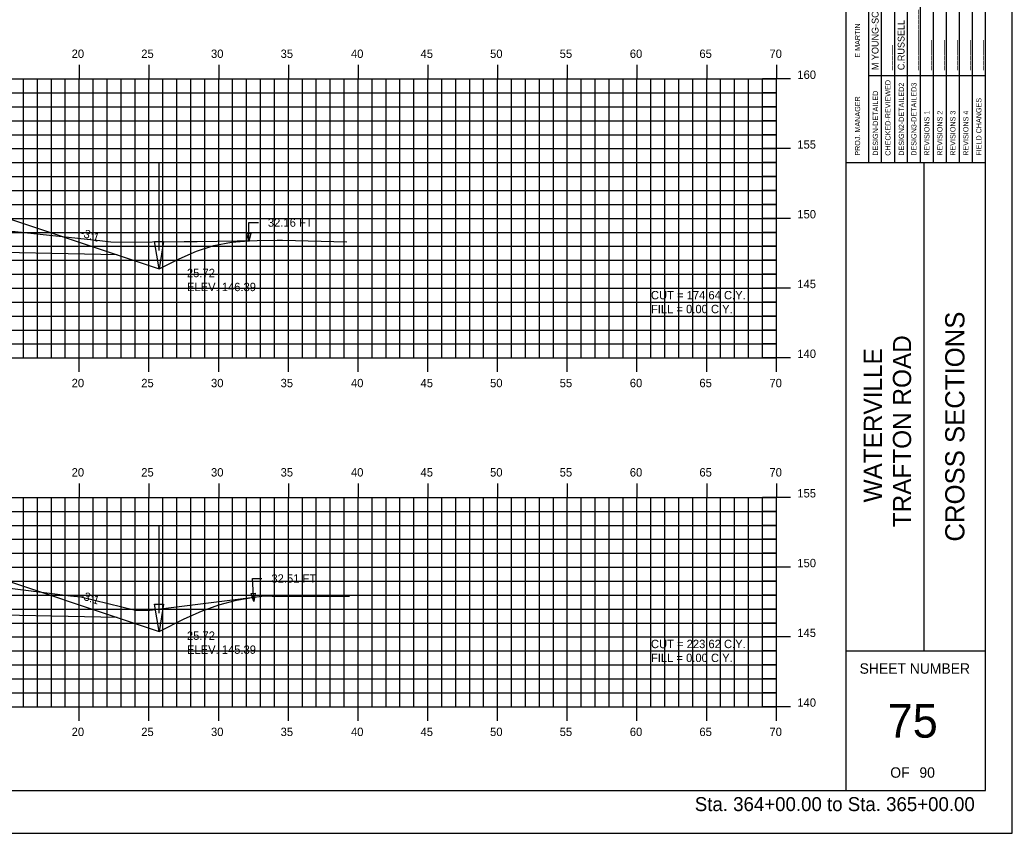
# Model space of a CAD drawing. Extents: x 1147190 to 1147360, y 608981 to 609091.
# Drawn here: x 1147288.7 to 1147359.8, y 608981.3 to 609039.6 of the extents above; entities that cross this region are included whole.
import ezdxf

# ---------------------------------------------------------------- set-up
doc = ezdxf.new("R2010")
doc.units = 0
for name, color, linetype in [('ANNOTATION', 7, 'Continuous'), ('BORDER', 7, 'Continuous'), ('D_Drainage_Ditch_Line', 7, 'Continuous'), ('D_Roadway_SlopeLines', 7, 'Continuous'), ('D_Roadway_SubGrade', 7, 'Continuous'), ('D_Text_Standard', 7, 'Continuous'), ('H_V ANNOTATION', 7, 'Continuous'), ('HIGHWAY_TITLE', 7, 'Continuous'), ('MAJOR', 7, 'Continuous'), ('MINOR', 7, 'Continuous'), ('PLOT BOUNDARY', 7, 'Continuous'), ('S_Roadway_Centerline', 7, 'Continuous')]:
    doc.layers.add(name, color=color, linetype=linetype)

msp = doc.modelspace()

# ---------------------------------------------------------------- linework, layer by layer
for points in [[(1147240.739, 609023.683), (1147241.989, 609023.617), (1147243.239, 609023.391), (1147244.489, 609023.006), (1147245.739, 609022.461), (1147247.216, 609021.723), (1147250.216, 609022.723), (1147257.94, 609025.297), (1147257.941, 609025.297), (1147261.941, 609025.457), (1147272.941, 609025.677), (1147283.941, 609025.457), (1147287.941, 609025.297), (1147295.664, 609022.723), (1147298.664, 609021.723), (1147300.098, 609022.439), (1147301.348, 609022.989), (1147302.598, 609023.387), (1147303.848, 609023.634), (1147305.098, 609023.73)], [(1147239.43, 608998.316), (1147240.68, 608998.262), (1147241.93, 608998.046), (1147243.18, 608997.666), (1147244.43, 608997.122), (1147247.216, 608995.729), (1147250.216, 608996.729), (1147257.94, 608999.304), (1147257.941, 608999.304), (1147261.941, 608999.464), (1147272.941, 608999.684), (1147283.941, 608999.464), (1147287.941, 608999.304), (1147295.664, 608996.729), (1147298.664, 608995.729), (1147300.456, 608996.625), (1147301.706, 608997.191), (1147302.956, 608997.64), (1147304.206, 608997.971), (1147305.456, 608998.184)]]:
    msp.add_lwpolyline(points)
at = {"layer": 'BORDER'}
for p, q in [((1147347.941, 608984.335), (1147347.941, 609089.335)), ((1147347.941, 609029.338), (1147357.941, 609029.338)), ((1147353.532, 608994.338), (1147353.532, 609029.338)), ((1147347.941, 608994.338), (1147357.941, 608994.338))]:
    msp.add_line(p, q, dxfattribs=at)
msp.add_lwpolyline([(1147197.941, 608984.335), (1147357.941, 608984.335), (1147357.941, 609089.335), (1147197.941, 609089.335)], close=True, dxfattribs=at)
for points in [[(1147350.489, 609029.341), (1147350.489, 609046.838)], [(1147351.42, 609046.838), (1147351.42, 609029.341)], [(1147352.352, 609029.341), (1147352.352, 609046.838)], [(1147353.284, 609029.341), (1147353.284, 609046.838)], [(1147354.215, 609029.341), (1147354.215, 609046.838)], [(1147355.147, 609029.341), (1147355.147, 609046.838)], [(1147356.079, 609029.341), (1147356.079, 609046.838)], [(1147357.01, 609029.341), (1147357.01, 609046.838)], [(1147349.557, 609029.341), (1147349.557, 609046.132)], [(1147349.556, 609035.588), (1147357.941, 609035.588)]]:
    msp.add_lwpolyline(points, dxfattribs=at)
at = {"layer": 'D_Drainage_Ditch_Line'}
for p, q in [((1147298.664, 609023.035), (1147298.665, 609029.278)), ((1147298.664, 608997.041), (1147298.665, 609003.285))]:
    msp.add_line(p, q, dxfattribs=at)
for points in [[(1147298.336, 609023.691), (1147298.992, 609023.691), (1147298.664, 609021.723)], [(1147298.336, 608997.698), (1147298.992, 608997.698), (1147298.664, 608995.729)]]:
    msp.add_lwpolyline(points, close=True, dxfattribs=at)
at = {"layer": 'D_Roadway_SlopeLines'}
for points in [[(1147298.664, 609021.723), (1147300.098, 609022.439), (1147301.348, 609022.989), (1147302.598, 609023.387), (1147303.848, 609023.634), (1147305.098, 609023.73)], [(1147295.664, 609022.723), (1147298.664, 609021.723)], [(1147298.664, 608995.729), (1147300.456, 608996.625), (1147301.706, 608997.191), (1147302.956, 608997.64), (1147304.206, 608997.971), (1147305.456, 608998.184)], [(1147295.664, 608996.729), (1147298.664, 608995.729)]]:
    msp.add_lwpolyline(points, dxfattribs=at)
at = {"layer": 'D_Roadway_SubGrade'}
for points in [[(1147283.941, 609025.04), (1147283.941, 609025.207), (1147287.941, 609025.047), (1147287.941, 609025.297), (1147287.941, 609025.297), (1147295.664, 609022.723), (1147283.941, 609022.957)], [(1147283.941, 608999.047), (1147283.941, 608999.214), (1147287.941, 608999.054), (1147287.941, 608999.304), (1147287.941, 608999.304), (1147295.664, 608996.729), (1147283.941, 608996.964)]]:
    msp.add_lwpolyline(points, close=True, dxfattribs=at)
at = {"layer": 'D_Text_Standard'}
for points in [[(1147305.098, 609023.689), (1147305.105, 609025.037), (1147305.785, 609025.037)], [(1147305.456, 608997.875), (1147305.36, 608999.527), (1147306.04, 608999.527)]]:
    msp.add_lwpolyline(points, dxfattribs=at)
for points in [[(1147305.098, 609023.689), (1147304.956, 609024.272), (1147305.247, 609024.271)], [(1147305.456, 608997.875), (1147305.277, 608998.447), (1147305.567, 608998.464)]]:
    msp.add_lwpolyline(points, close=True, dxfattribs=at)
at = {"layer": 'MAJOR'}
for p, q in [((1147292.941, 609036.337), (1147292.941, 609035.335)), ((1147297.941, 609036.337), (1147297.941, 609035.335)), ((1147302.941, 609036.337), (1147302.941, 609035.335)), ((1147307.941, 609036.337), (1147307.941, 609035.335)), ((1147312.941, 609036.337), (1147312.941, 609035.335)), ((1147317.941, 609036.337), (1147317.941, 609035.335)), ((1147322.941, 609036.337), (1147322.941, 609035.335)), ((1147327.941, 609036.337), (1147327.941, 609035.335)), ((1147332.941, 609036.337), (1147332.941, 609035.335)), ((1147337.941, 609036.337), (1147337.941, 609035.335)), ((1147342.941, 609036.337), (1147342.941, 609035.335)), ((1147202.941, 609035.335), (1147342.941, 609035.335)), ((1147202.941, 609035.335), (1147342.941, 609035.335)), ((1147292.941, 609015.335), (1147292.941, 609035.335)), ((1147297.941, 609015.335), (1147297.941, 609035.335)), ((1147302.941, 609015.335), (1147302.941, 609035.335)), ((1147307.941, 609015.335), (1147307.941, 609035.335)), ((1147312.941, 609015.335), (1147312.941, 609035.335)), ((1147317.941, 609015.335), (1147317.941, 609035.335)), ((1147322.941, 609015.335), (1147322.941, 609035.335)), ((1147327.941, 609015.335), (1147327.941, 609035.335)), ((1147332.941, 609015.335), (1147332.941, 609035.335)), ((1147337.941, 609015.335), (1147337.941, 609035.335)), ((1147343.943, 609035.335), (1147341.939, 609035.335)), ((1147342.941, 609015.335), (1147342.941, 609035.335)), ((1147342.941, 609015.335), (1147342.941, 609035.335)), ((1147202.941, 609030.335), (1147342.941, 609030.335)), ((1147343.943, 609030.335), (1147341.939, 609030.335)), ((1147202.941, 609025.335), (1147342.941, 609025.335)), ((1147343.943, 609025.335), (1147341.939, 609025.335)), ((1147202.941, 609020.335), (1147342.941, 609020.335)), ((1147343.943, 609020.335), (1147341.939, 609020.335)), ((1147202.941, 609015.335), (1147342.941, 609015.335)), ((1147202.941, 609015.335), (1147342.941, 609015.335)), ((1147292.941, 609014.333), (1147292.941, 609015.335)), ((1147297.941, 609014.333), (1147297.941, 609015.335)), ((1147302.941, 609014.333), (1147302.941, 609015.335)), ((1147307.941, 609014.333), (1147307.941, 609015.335)), ((1147312.941, 609014.333), (1147312.941, 609015.335)), ((1147317.941, 609014.333), (1147317.941, 609015.335)), ((1147322.941, 609014.333), (1147322.941, 609015.335)), ((1147327.941, 609014.333), (1147327.941, 609015.335)), ((1147332.941, 609014.333), (1147332.941, 609015.335)), ((1147337.941, 609014.333), (1147337.941, 609015.335)), ((1147343.943, 609015.335), (1147341.939, 609015.335)), ((1147342.941, 609014.333), (1147342.941, 609015.335)), ((1147292.941, 609006.337), (1147292.941, 609005.335)), ((1147297.941, 609006.337), (1147297.941, 609005.335)), ((1147302.941, 609006.337), (1147302.941, 609005.335)), ((1147307.941, 609006.337), (1147307.941, 609005.335)), ((1147312.941, 609006.337), (1147312.941, 609005.335)), ((1147317.941, 609006.337), (1147317.941, 609005.335)), ((1147322.941, 609006.337), (1147322.941, 609005.335)), ((1147327.941, 609006.337), (1147327.941, 609005.335)), ((1147332.941, 609006.337), (1147332.941, 609005.335)), ((1147337.941, 609006.337), (1147337.941, 609005.335)), ((1147342.941, 609006.337), (1147342.941, 609005.335)), ((1147202.941, 609005.335), (1147342.941, 609005.335)), ((1147202.941, 609005.335), (1147342.941, 609005.335)), ((1147292.941, 608990.335), (1147292.941, 609005.335)), ((1147297.941, 608990.335), (1147297.941, 609005.335)), ((1147302.941, 608990.335), (1147302.941, 609005.335)), ((1147307.941, 608990.335), (1147307.941, 609005.335)), ((1147312.941, 608990.335), (1147312.941, 609005.335)), ((1147317.941, 608990.335), (1147317.941, 609005.335)), ((1147322.941, 608990.335), (1147322.941, 609005.335)), ((1147327.941, 608990.335), (1147327.941, 609005.335)), ((1147332.941, 608990.335), (1147332.941, 609005.335)), ((1147337.941, 608990.335), (1147337.941, 609005.335)), ((1147343.943, 609005.335), (1147341.939, 609005.335)), ((1147342.941, 608990.335), (1147342.941, 609005.335)), ((1147342.941, 608990.335), (1147342.941, 609005.335)), ((1147202.941, 609000.335), (1147342.941, 609000.335)), ((1147343.943, 609000.335), (1147341.939, 609000.335)), ((1147202.941, 608995.335), (1147342.941, 608995.335)), ((1147343.943, 608995.335), (1147341.939, 608995.335)), ((1147202.941, 608990.335), (1147342.941, 608990.335)), ((1147202.941, 608990.335), (1147342.941, 608990.335)), ((1147292.941, 608989.333), (1147292.941, 608990.335)), ((1147297.941, 608989.333), (1147297.941, 608990.335)), ((1147302.941, 608989.333), (1147302.941, 608990.335)), ((1147307.941, 608989.333), (1147307.941, 608990.335)), ((1147312.941, 608989.333), (1147312.941, 608990.335)), ((1147317.941, 608989.333), (1147317.941, 608990.335)), ((1147322.941, 608989.333), (1147322.941, 608990.335)), ((1147327.941, 608989.333), (1147327.941, 608990.335)), ((1147332.941, 608989.333), (1147332.941, 608990.335)), ((1147337.941, 608989.333), (1147337.941, 608990.335)), ((1147343.943, 608990.335), (1147341.939, 608990.335)), ((1147342.941, 608989.333), (1147342.941, 608990.335))]:
    msp.add_line(p, q, dxfattribs=at)
at = {"layer": 'MINOR'}
for p, q in [((1147288.941, 609015.335), (1147288.941, 609035.335)), ((1147289.941, 609015.335), (1147289.941, 609035.335)), ((1147290.941, 609015.335), (1147290.941, 609035.335)), ((1147291.941, 609015.335), (1147291.941, 609035.335)), ((1147293.941, 609015.335), (1147293.941, 609035.335)), ((1147294.941, 609015.335), (1147294.941, 609035.335)), ((1147295.941, 609015.335), (1147295.941, 609035.335)), ((1147296.941, 609015.335), (1147296.941, 609035.335)), ((1147298.941, 609015.335), (1147298.941, 609035.335)), ((1147299.941, 609015.335), (1147299.941, 609035.335)), ((1147300.941, 609015.335), (1147300.941, 609035.335)), ((1147301.941, 609015.335), (1147301.941, 609035.335)), ((1147303.941, 609015.335), (1147303.941, 609035.335)), ((1147304.941, 609015.335), (1147304.941, 609035.335)), ((1147305.941, 609015.335), (1147305.941, 609035.335)), ((1147306.941, 609015.335), (1147306.941, 609035.335)), ((1147308.941, 609015.335), (1147308.941, 609035.335)), ((1147309.941, 609015.335), (1147309.941, 609035.335)), ((1147310.941, 609015.335), (1147310.941, 609035.335)), ((1147311.941, 609015.335), (1147311.941, 609035.335)), ((1147313.941, 609015.335), (1147313.941, 609035.335)), ((1147314.941, 609015.335), (1147314.941, 609035.335)), ((1147315.941, 609015.335), (1147315.941, 609035.335)), ((1147316.941, 609015.335), (1147316.941, 609035.335)), ((1147318.941, 609015.335), (1147318.941, 609035.335)), ((1147319.941, 609015.335), (1147319.941, 609035.335)), ((1147320.941, 609015.335), (1147320.941, 609035.335)), ((1147321.941, 609015.335), (1147321.941, 609035.335)), ((1147323.941, 609015.335), (1147323.941, 609035.335)), ((1147324.941, 609015.335), (1147324.941, 609035.335)), ((1147325.941, 609015.335), (1147325.941, 609035.335)), ((1147326.941, 609015.335), (1147326.941, 609035.335)), ((1147328.941, 609015.335), (1147328.941, 609035.335)), ((1147329.941, 609015.335), (1147329.941, 609035.335)), ((1147330.941, 609015.335), (1147330.941, 609035.335)), ((1147331.941, 609015.335), (1147331.941, 609035.335)), ((1147333.941, 609015.335), (1147333.941, 609035.335)), ((1147334.941, 609015.335), (1147334.941, 609035.335)), ((1147335.941, 609015.335), (1147335.941, 609035.335)), ((1147336.941, 609015.335), (1147336.941, 609035.335)), ((1147338.941, 609015.335), (1147338.941, 609035.335)), ((1147339.941, 609015.335), (1147339.941, 609035.335)), ((1147340.941, 609015.335), (1147340.941, 609035.335)), ((1147341.941, 609015.335), (1147341.941, 609035.335)), ((1147202.941, 609034.335), (1147342.941, 609034.335)), ((1147342.941, 609034.335), (1147341.939, 609034.335)), ((1147202.941, 609033.335), (1147342.941, 609033.335)), ((1147342.941, 609033.335), (1147341.939, 609033.335)), ((1147202.941, 609032.335), (1147342.941, 609032.335)), ((1147342.941, 609032.335), (1147341.939, 609032.335)), ((1147202.941, 609031.335), (1147342.941, 609031.335)), ((1147342.941, 609031.335), (1147341.939, 609031.335)), ((1147202.941, 609029.335), (1147342.941, 609029.335)), ((1147342.941, 609029.335), (1147341.939, 609029.335)), ((1147202.941, 609028.335), (1147342.941, 609028.335)), ((1147342.941, 609028.335), (1147341.939, 609028.335)), ((1147202.941, 609027.335), (1147342.941, 609027.335)), ((1147342.941, 609027.335), (1147341.939, 609027.335)), ((1147202.941, 609026.335), (1147342.941, 609026.335)), ((1147342.941, 609026.335), (1147341.939, 609026.335)), ((1147202.941, 609024.335), (1147342.941, 609024.335)), ((1147342.941, 609024.335), (1147341.939, 609024.335)), ((1147202.941, 609023.335), (1147342.941, 609023.335)), ((1147342.941, 609023.335), (1147341.939, 609023.335)), ((1147202.941, 609022.335), (1147342.941, 609022.335)), ((1147342.941, 609022.335), (1147341.939, 609022.335)), ((1147202.941, 609021.335), (1147342.941, 609021.335)), ((1147342.941, 609021.335), (1147341.939, 609021.335)), ((1147202.941, 609019.335), (1147342.941, 609019.335)), ((1147342.941, 609019.335), (1147341.939, 609019.335)), ((1147202.941, 609018.335), (1147342.941, 609018.335)), ((1147342.941, 609018.335), (1147341.939, 609018.335)), ((1147202.941, 609017.335), (1147342.941, 609017.335)), ((1147342.941, 609017.335), (1147341.939, 609017.335)), ((1147202.941, 609016.335), (1147342.941, 609016.335)), ((1147342.941, 609016.335), (1147341.939, 609016.335)), ((1147288.941, 608990.335), (1147288.941, 609005.335)), ((1147289.941, 608990.335), (1147289.941, 609005.335)), ((1147290.941, 608990.335), (1147290.941, 609005.335)), ((1147291.941, 608990.335), (1147291.941, 609005.335)), ((1147293.941, 608990.335), (1147293.941, 609005.335)), ((1147294.941, 608990.335), (1147294.941, 609005.335)), ((1147295.941, 608990.335), (1147295.941, 609005.335)), ((1147296.941, 608990.335), (1147296.941, 609005.335)), ((1147298.941, 608990.335), (1147298.941, 609005.335)), ((1147299.941, 608990.335), (1147299.941, 609005.335)), ((1147300.941, 608990.335), (1147300.941, 609005.335)), ((1147301.941, 608990.335), (1147301.941, 609005.335)), ((1147303.941, 608990.335), (1147303.941, 609005.335)), ((1147304.941, 608990.335), (1147304.941, 609005.335)), ((1147305.941, 608990.335), (1147305.941, 609005.335)), ((1147306.941, 608990.335), (1147306.941, 609005.335)), ((1147308.941, 608990.335), (1147308.941, 609005.335)), ((1147309.941, 608990.335), (1147309.941, 609005.335)), ((1147310.941, 608990.335), (1147310.941, 609005.335)), ((1147311.941, 608990.335), (1147311.941, 609005.335)), ((1147313.941, 608990.335), (1147313.941, 609005.335)), ((1147314.941, 608990.335), (1147314.941, 609005.335)), ((1147315.941, 608990.335), (1147315.941, 609005.335)), ((1147316.941, 608990.335), (1147316.941, 609005.335)), ((1147318.941, 608990.335), (1147318.941, 609005.335)), ((1147319.941, 608990.335), (1147319.941, 609005.335)), ((1147320.941, 608990.335), (1147320.941, 609005.335)), ((1147321.941, 608990.335), (1147321.941, 609005.335)), ((1147323.941, 608990.335), (1147323.941, 609005.335)), ((1147324.941, 608990.335), (1147324.941, 609005.335)), ((1147325.941, 608990.335), (1147325.941, 609005.335)), ((1147326.941, 608990.335), (1147326.941, 609005.335)), ((1147328.941, 608990.335), (1147328.941, 609005.335)), ((1147329.941, 608990.335), (1147329.941, 609005.335)), ((1147330.941, 608990.335), (1147330.941, 609005.335)), ((1147331.941, 608990.335), (1147331.941, 609005.335)), ((1147333.941, 608990.335), (1147333.941, 609005.335)), ((1147334.941, 608990.335), (1147334.941, 609005.335)), ((1147335.941, 608990.335), (1147335.941, 609005.335)), ((1147336.941, 608990.335), (1147336.941, 609005.335)), ((1147338.941, 608990.335), (1147338.941, 609005.335)), ((1147339.941, 608990.335), (1147339.941, 609005.335)), ((1147340.941, 608990.335), (1147340.941, 609005.335)), ((1147341.941, 608990.335), (1147341.941, 609005.335)), ((1147202.941, 609004.335), (1147342.941, 609004.335)), ((1147342.941, 609004.335), (1147341.939, 609004.335)), ((1147202.941, 609003.335), (1147342.941, 609003.335)), ((1147342.941, 609003.335), (1147341.939, 609003.335)), ((1147202.941, 609002.335), (1147342.941, 609002.335)), ((1147342.941, 609002.335), (1147341.939, 609002.335)), ((1147202.941, 609001.335), (1147342.941, 609001.335)), ((1147342.941, 609001.335), (1147341.939, 609001.335)), ((1147202.941, 608999.335), (1147342.941, 608999.335)), ((1147342.941, 608999.335), (1147341.939, 608999.335)), ((1147202.941, 608998.335), (1147342.941, 608998.335)), ((1147342.941, 608998.335), (1147341.939, 608998.335)), ((1147202.941, 608997.335), (1147342.941, 608997.335)), ((1147342.941, 608997.335), (1147341.939, 608997.335)), ((1147202.941, 608996.335), (1147342.941, 608996.335)), ((1147342.941, 608996.335), (1147341.939, 608996.335)), ((1147202.941, 608994.335), (1147342.941, 608994.335)), ((1147342.941, 608994.335), (1147341.939, 608994.335)), ((1147202.941, 608993.335), (1147342.941, 608993.335)), ((1147342.941, 608993.335), (1147341.939, 608993.335)), ((1147202.941, 608992.335), (1147342.941, 608992.335)), ((1147342.941, 608992.335), (1147341.939, 608992.335)), ((1147202.941, 608991.335), (1147342.941, 608991.335)), ((1147342.941, 608991.335), (1147341.939, 608991.335))]:
    msp.add_line(p, q, dxfattribs=at)
at = {"layer": 'PLOT BOUNDARY'}
msp.add_lwpolyline([(1147189.848, 608981.276), (1147359.848, 608981.276), (1147359.848, 609091.276), (1147189.848, 609091.276)], close=True, dxfattribs=at)
at = {"layer": 'S_Roadway_Centerline'}
for points in [[(1147215.532, 609023.394), (1147227.867, 609023.538), (1147246.188, 609023.744), (1147249.793, 609023.75), (1147254.992, 609023.718), (1147256.149, 609023.993), (1147258.083, 609024.547), (1147259.081, 609024.551), (1147260.862, 609024.571), (1147268.511, 609024.64), (1147272.288, 609024.696), (1147275.928, 609024.661), (1147283.359, 609024.561), (1147287.032, 609024.5), (1147287.423, 609024.486), (1147294.421, 609023.747), (1147295.199, 609023.66), (1147295.905, 609023.638), (1147300.455, 609023.669), (1147301.408, 609023.67), (1147307.138, 609023.764), (1147307.507, 609023.763), (1147312.134, 609023.662)], [(1147218.846, 608997.864), (1147241.122, 608998.353), (1147247.885, 608998.514), (1147248.984, 608998.516), (1147254.873, 608998.314), (1147257.094, 608998.713), (1147257.502, 608998.83), (1147259.688, 608998.949), (1147260.064, 608998.953), (1147270.445, 608999.103), (1147271.787, 608999.116), (1147281.744, 608998.963), (1147282.951, 608998.947), (1147286.36, 608998.968), (1147286.809, 608998.965), (1147292.313, 608998.283), (1147293.044, 608998.205), (1147296.983, 608997.246), (1147297.425, 608997.25), (1147298.007, 608997.262), (1147306.226, 608998.28), (1147306.772, 608998.268), (1147312.322, 608998.262)]]:
    msp.add_lwpolyline(points, dxfattribs=at)

# ---------------------------------------------------------------- texts
at = {"layer": 'ANNOTATION'}
for p in [(1147292.952, 609024.081), (1147292.952, 608998.087)]:
    msp.add_text('-3:1', height=0.6, rotation=341.56521, dxfattribs=at).set_placement(p)
at = {"layer": 'BORDER'}
for s, height, p in [('M YOUNG-SCAGGS', 0.48455, (1147350.264, 609035.961)), ('____________', 0.48455, (1147353.022, 609035.961)), ('E MARTIN', 0.3727, (1147348.945, 609036.855)), ('C.RUSSELL', 0.4845, (1147352.127, 609035.961)), ('_____', 0.4845, (1147351.158, 609035.961)), ('______', 0.4845, (1147353.953, 609035.961)), ('______', 0.4845, (1147354.885, 609035.961)), ('______', 0.4845, (1147355.817, 609035.961)), ('______', 0.4845, (1147356.749, 609035.961)), ('______', 0.4845, (1147357.68, 609035.961)), ('CHECKED-REVIEWED', 0.37275, (1147351.122, 609029.826)), ('DESIGN3-DETAILED3', 0.37275, (1147352.985, 609029.826)), ('DESIGN-DETAILED', 0.37275, (1147350.228, 609029.826)), ('DESIGN2-DETAILED2', 0.37275, (1147352.091, 609029.826)), ('PROJ. MANAGER', 0.37275, (1147348.945, 609029.826)), ('FIELD CHANGES', 0.37275, (1147357.644, 609029.826)), ('REVISIONS 1', 0.37275, (1147353.917, 609029.826)), ('REVISIONS 2', 0.37275, (1147354.849, 609029.826)), ('REVISIONS 3', 0.37275, (1147355.781, 609029.826)), ('REVISIONS 4', 0.37275, (1147356.712, 609029.826)), ('CROSS SECTIONS', 1.37787, (1147356.426, 609002.172))]:
    msp.add_text(s, height=height, rotation=90, dxfattribs=at).set_placement(p)
for s, height, p in [('SHEET NUMBER', 0.74527, (1147348.907, 608992.701)), ('75', 2.4194, (1147350.917, 608988.118)), ('OF', 0.7453, (1147351.108, 608985.248)), ('90', 0.7453, (1147353.198, 608985.248))]:
    msp.add_text(s, height=height, dxfattribs=at).set_placement(p)
at = {"layer": 'D_Text_Standard'}
for s, p in [('32.16 FT', (1147306.465, 609024.737)), ('25.72', (1147300.664, 609021.123)), ('ELEV. 146.39', (1147300.664, 609020.121)), ('CUT = 174.64 C.Y.', (1147333.941, 609019.535)), ('FILL = 0.00 C.Y.', (1147333.941, 609018.539)), ('32.51 FT', (1147306.72, 608999.227)), ('25.72', (1147300.664, 608995.129)), ('CUT = 223.62 C.Y.', (1147333.941, 608994.535)), ('ELEV. 145.39', (1147300.664, 608994.127)), ('FILL = 0.00 C.Y.', (1147333.941, 608993.539))]:
    msp.add_text(s, height=0.6, dxfattribs=at).set_placement(p)
at = {"layer": 'H_V ANNOTATION'}
for s, height, p in [('20', 0.6, (1147292.395, 609036.835)), ('25', 0.6, (1147297.387, 609036.835)), ('30', 0.6, (1147302.39, 609036.835)), ('35', 0.6, (1147307.382, 609036.835)), ('40', 0.6, (1147312.427, 609036.835)), ('45', 0.6, (1147317.419, 609036.835)), ('50', 0.6, (1147322.406, 609036.835)), ('55', 0.6, (1147327.398, 609036.835)), ('60', 0.6, (1147332.427, 609036.835)), ('65', 0.6, (1147337.419, 609036.835)), ('70', 0.6, (1147342.443, 609036.835)), ('160', 0.6, (1147344.441, 609035.335)), ('155', 0.6, (1147344.441, 609030.335)), ('150', 0.6, (1147344.441, 609025.335)), ('145', 0.6, (1147344.441, 609020.335)), ('140', 0.6, (1147344.441, 609015.335)), ('20', 0.6, (1147292.395, 609013.235)), ('25', 0.6, (1147297.387, 609013.235)), ('30', 0.6, (1147302.39, 609013.235)), ('35', 0.6, (1147307.382, 609013.235)), ('40', 0.6, (1147312.427, 609013.235)), ('45', 0.6, (1147317.419, 609013.235)), ('50', 0.6, (1147322.406, 609013.235)), ('55', 0.6, (1147327.398, 609013.235)), ('60', 0.6, (1147332.427, 609013.235)), ('65', 0.6, (1147337.419, 609013.235)), ('70', 0.6, (1147342.443, 609013.235)), ('20', 0.6, (1147292.395, 609006.835)), ('25', 0.6, (1147297.387, 609006.835)), ('30', 0.6, (1147302.39, 609006.835)), ('35', 0.6, (1147307.382, 609006.835)), ('40', 0.6, (1147312.427, 609006.835)), ('45', 0.6, (1147317.419, 609006.835)), ('50', 0.6, (1147322.406, 609006.835)), ('55', 0.6, (1147327.398, 609006.835)), ('60', 0.6, (1147332.427, 609006.835)), ('65', 0.6, (1147337.419, 609006.835)), ('70', 0.6, (1147342.443, 609006.835)), ('155', 0.6, (1147344.441, 609005.335)), ('150', 0.6, (1147344.441, 609000.335)), ('145', 0.6, (1147344.441, 608995.335)), ('140', 0.6, (1147344.441, 608990.335)), ('20', 0.6, (1147292.395, 608988.235)), ('25', 0.6, (1147297.387, 608988.235)), ('30', 0.6, (1147302.39, 608988.235)), ('35', 0.6, (1147307.382, 608988.235)), ('40', 0.6, (1147312.427, 608988.235)), ('45', 0.6, (1147317.419, 608988.235)), ('50', 0.6, (1147322.406, 608988.235)), ('55', 0.6, (1147327.398, 608988.235)), ('60', 0.6, (1147332.427, 608988.235)), ('65', 0.6, (1147337.419, 608988.235)), ('70', 0.6, (1147342.443, 608988.235)), ('Sta. 364+00.00 to Sta. 365+00.00', 1.0002, (1147337.087, 608982.855))]:
    msp.add_text(s, height=height, dxfattribs=at).set_placement(p)
at = {"layer": 'HIGHWAY_TITLE'}
for s, height, p in [('TRAFTON ROAD', 1.30428, (1147352.6, 609003.201)), ('WATERVILLE', 1.3043, (1147350.513, 609004.98))]:
    msp.add_text(s, height=height, rotation=90, dxfattribs=at).set_placement(p)

doc.saveas('drawing.dxf')
